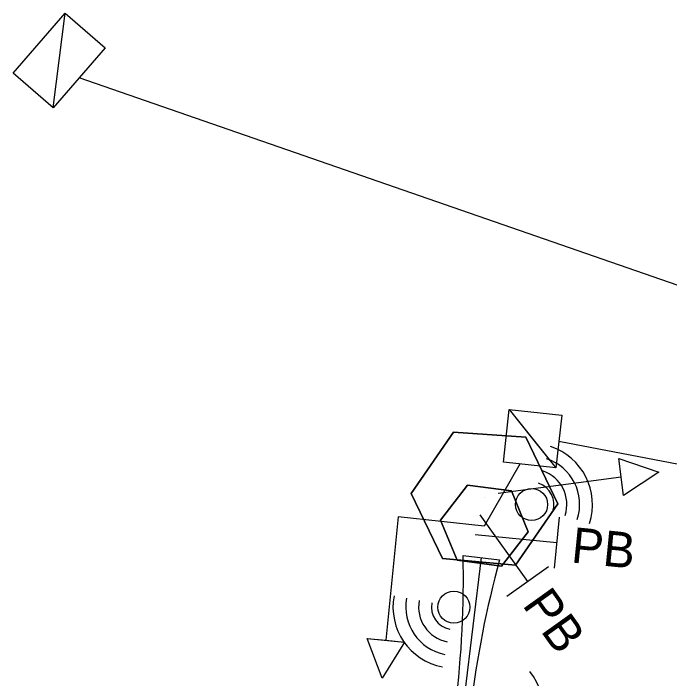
# Model space of a CAD drawing. Extents: x -200 to 1730068, y -325 to 756043.
# Drawn here: x 1725385.43 to 1725426.41, y 658666.3 to 658707.85 of the extents above; entities that cross this region are included whole.
import ezdxf

# ---------------------------------------------------------------- set-up
doc = ezdxf.new("R2010")
doc.units = 0
for name, color, linetype in [('DESIGN - TRAFFIC CONTROL PERMANENT - Signal Poles', 7, 'Continuous'), ('DESIGN - TRAFFIC CONTROL PERMANENT - Signal Poles 50 Scale', 7, 'Continuous'), ('DESIGN - TRAFFIC CONTROL PERMANENT - Signalization', 7, 'Continuous')]:
    doc.layers.add(name, color=color, linetype=linetype)

msp = doc.modelspace()

# ---------------------------------------------------------------- linework, layer by layer
at = {"layer": 'DESIGN - TRAFFIC CONTROL PERMANENT - Signal Poles'}
msp.add_line((1725414.829, 658675.825), (1725414.829, 658675.825), dxfattribs=at)
msp.add_lwpolyline([(1725413.779, 658678.387), (1725416.544, 658678.018), (1725417.565, 658675.46), (1725415.917, 658673.319), (1725413.152, 658673.688), (1725412.093, 658676.19)], close=True, dxfattribs=at)
msp.add_lwpolyline([(1725413.779, 658678.387), (1725412.093, 658676.19), (1725413.152, 658673.688), (1725415.917, 658673.319), (1725417.565, 658675.46), (1725416.544, 658678.018), (1725413.779, 658678.387)], dxfattribs=at)
at = {"layer": 'DESIGN - TRAFFIC CONTROL PERMANENT - Signal Poles 50 Scale'}
msp.add_line((1725414.822, 658677.589), (1725414.822, 658677.589), dxfattribs=at)
msp.add_lwpolyline([(1725419.422, 658677.224), (1725416.792, 658673.389), (1725412.22, 658673.796), (1725410.277, 658677.857), (1725412.907, 658681.692), (1725417.424, 658681.383)], close=True, dxfattribs=at)
msp.add_lwpolyline([(1725419.422, 658677.224), (1725417.424, 658681.383), (1725412.907, 658681.692), (1725410.277, 658677.857), (1725412.22, 658673.796), (1725416.792, 658673.389), (1725419.422, 658677.224)], dxfattribs=at)
at = {"layer": 'DESIGN - TRAFFIC CONTROL PERMANENT - Signalization'}
for p, q in [((1725387.929, 658701.944), (1725388.67, 658707.847)), ((1725473.465, 658674.685), (1725389.548, 658703.817)), ((1725416.388, 658683.103), (1725419.309, 658679.463)), ((1725417.849, 658681.283), (1725417.849, 658681.283)), ((1725469.25, 658671.577), (1725419.489, 658681.103)), ((1725417.081, 658679.728), (1725414.829, 658675.825)), ((1725414.551, 658676.528), (1725417.534, 658672.355)), ((1725414.829, 658675.825), (1725409.456, 658676.399)), ((1725419.52, 658676.387), (1725419.201, 658673.208)), ((1725414.256, 658675.309), (1725419.361, 658674.798)), ((1725413.512, 658673.995), (1725415.789, 658673.716)), ((1725414.65, 658673.856), (1725409.8, 658634.151)), ((1725418.834, 658673.284), (1725416.235, 658671.426))]:
    msp.add_line(p, q, dxfattribs=at)
for points in [[(1725387.929, 658701.944), (1725385.433, 658704.102), (1725388.67, 658707.847), (1725391.166, 658705.689)], [(1725391.166, 658705.689), (1725387.929, 658701.944), (1725388.299, 658704.896), (1725388.67, 658707.847)], [(1725416.388, 658683.103), (1725419.669, 658682.743), (1725419.309, 658679.463), (1725416.029, 658679.822)], [(1725416.029, 658679.822), (1725416.388, 658683.103), (1725417.849, 658681.283), (1725419.309, 658679.463)], [(1725423.533, 658677.733), (1725423.228, 658680.053), (1725425.731, 658679.202)], [(1725407.529, 658668.812), (1725409.857, 658668.581), (1725408.459, 658666.338)]]:
    msp.add_lwpolyline(points, close=True, dxfattribs=at)
for points in [[(1725415.707, 658677.884), (1725423.381, 658678.893), (1725423.228, 658680.053), (1725425.731, 658679.202), (1725423.533, 658677.733), (1725423.381, 658678.893)], [(1725409.456, 658676.399), (1725408.693, 658668.696), (1725409.857, 658668.581), (1725408.459, 658666.338), (1725407.529, 658668.812), (1725408.693, 658668.696)]]:
    msp.add_lwpolyline(points, dxfattribs=at)
for centre in [(1725417.789, 658677.175), (1725412.936, 658670.764)]:
    msp.add_circle(centre, 1, dxfattribs=at)
for centre, radius, start, end in [((1725417.789, 658677.175), 3.8, 341.8822, 71.8822), ((1725417.789, 658677.175), 3, 341.8822, 71.8822), ((1725417.789, 658677.175), 2.2, 341.8822, 71.8822), ((1725417.789, 658677.175), 1.4, 341.8822, 71.8822), ((1725412.936, 658670.764), 3.8, 169.2788, 259.2788), ((1725412.936, 658670.764), 3, 169.2788, 259.2788), ((1725412.936, 658670.764), 2.2, 169.2788, 259.2788), ((1725412.936, 658670.764), 1.4, 169.2788, 259.2788), ((1725414.702, 658664.398), 3.8, 308.2174, 38.2174)]:
    msp.add_arc(centre, radius, start, end, dxfattribs=at)
for centre, major_axis, start_param, end_param in [((1725377.736, 658669.151), (5.755, 47.106), 4.708264, 4.906342), ((1725449.347, 658660.402), (-5.755, -47.106), 4.518436, 4.716514)]:
    msp.add_ellipse(centre, major_axis=major_axis, ratio=0.75, start_param=start_param, end_param=end_param, dxfattribs=at)

# ---------------------------------------------------------------- texts
for rotation, p in [(354.2759, (1725420.209, 658673.559)), (305.5624, (1725417.164, 658670.901))]:
    msp.add_text('PB', height=2.2147, rotation=rotation, dxfattribs=at).set_placement(p)

doc.saveas('drawing.dxf')
